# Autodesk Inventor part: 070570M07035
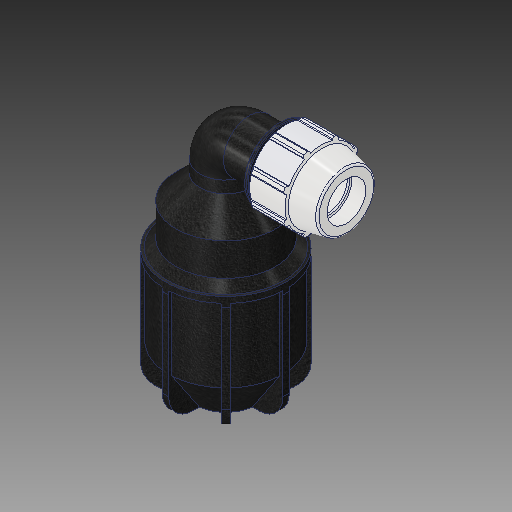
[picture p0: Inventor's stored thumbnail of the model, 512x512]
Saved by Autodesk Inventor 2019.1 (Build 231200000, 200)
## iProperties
Created: 2017-02
Part Number: 070570M07035
Material: PVC-Piping
Description: PLASSON PLASS4 90° ELBOW 3/4'' - 1.22
Document SubType Name: Modeling
Designer: KIM
Mass: 92.6774 g
Surface Area: 199.44 cm^2
Volume: 66.1981 cm^3
Density: 1.4 g/cm^3
Appearance: PTFE
Author: KIM
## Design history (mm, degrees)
derived "070570M0.ipt"
feature "Solid1::070570M0.ipt"
tag "TaggingFeature1"
body "Solid1"
other parameters: "d2" = 26.6, "d4" = 11.86543, "d5" = 16.6116, "d7" = 54.102, "d8" = 35.68618, "d9" = 11.86543, "d11" = 2.37309, "d12" = 43.2816, "d13" = 120 deg, "d14" = 39.9, "d15" = 12 deg, "d16" = 48.6918, "d18" = 1.33, "d19" = 35 deg, "d20" = 17.5 deg, "d21" = 50.31486, "d23" = 0, "d25" = 360 deg, "d27" = 1.08204, "d42" = 24.9174, "d43" = 1.62306, "d46" = 0.798, "d53" = 0.532, "d67" = 2.7051, "d70" = 23.94, "d71" = 59.944, "d73" = 83.058, "d74" = 90 deg, "d75" = 30.988, "d76" = 83.058, "d77" = 152.908, "d78" = 0.83058, "d80" = 23.94, "d82" = 112.014, "d84" = 78.9051, "d85" = 135 deg, "d86" = 4.1529, "d88" = 112.014, "d89" = 4.1529, "d90" = 135 deg, "d91" = 84.0105, "d92" = 24.46528, "d93" = 28.0035, "d94" = 4.1529, "d95" = 5.6007, "d97" = 4.32816, "d98" = 0, "d100" = 360 deg, "d102" = 91.3638, "d103" = 16.6116, "d104" = 6.64464, "d105" = 0, "d107" = 16.2306, "d108" = 0, "d109" = 0, "d110" = 2.37309, "d_" = 26.6, "E_" = 54.102, "A_" = 83.058, "l_" = 59.944, "d_1" = 30.988, "E_1" = 83.058, "l_1" = 112.014, "A_1" = 152.908, "d106" = 35.68618
